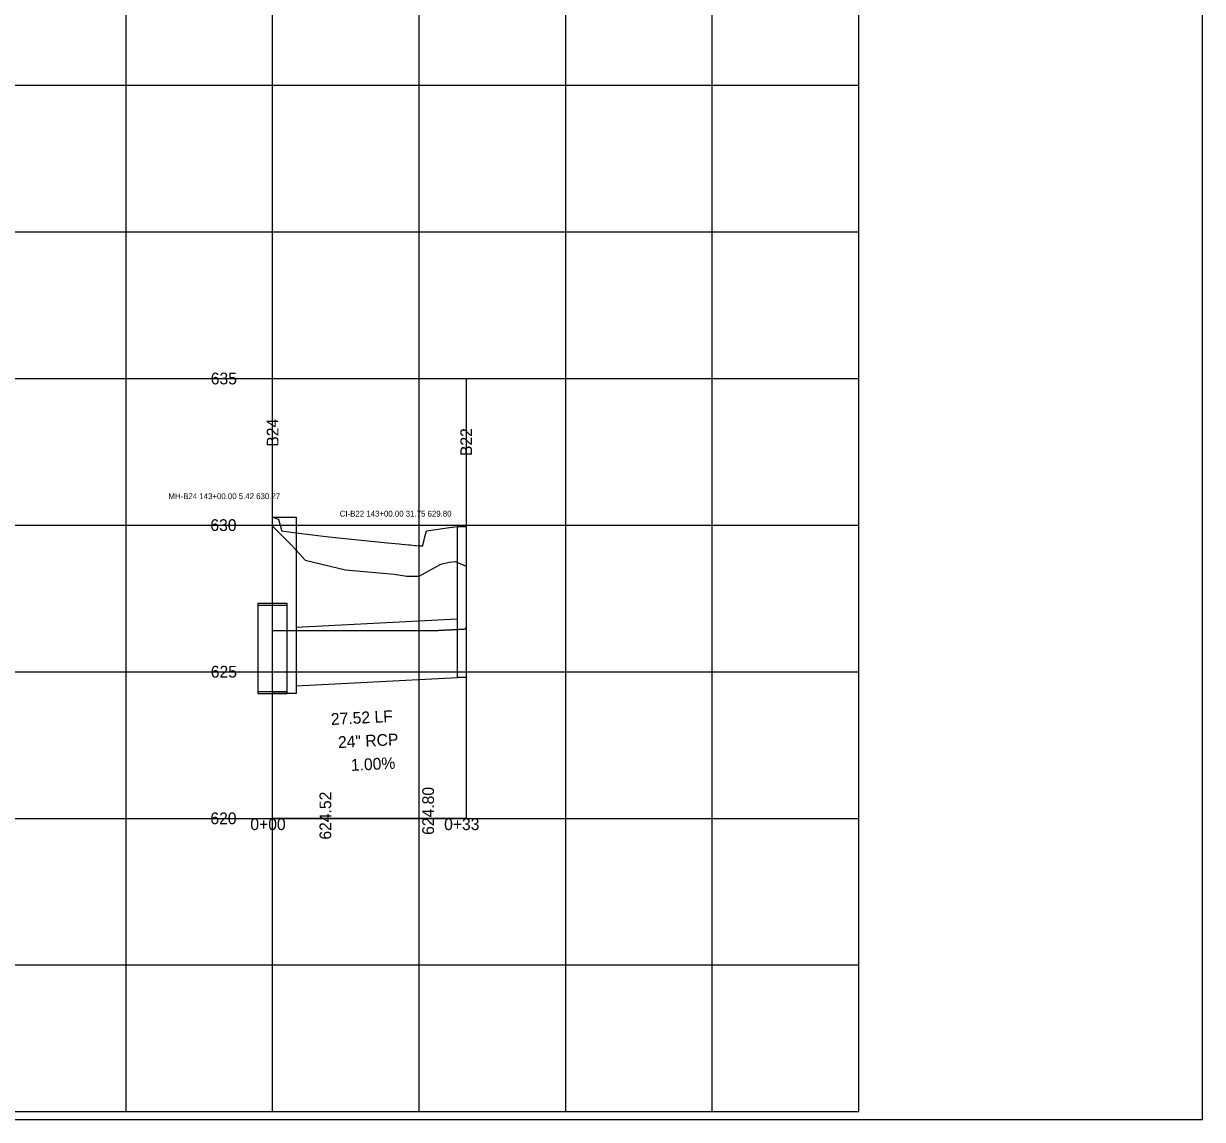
# Model space of a CAD drawing. Extents: x 2253035 to 2279930, y 13774972 to 13793443.
# Drawn here: x 2276931.9 to 2277133, y 13792491.3 to 13792678.1 of the extents above; entities that cross this region are included whole.
import ezdxf

# ---------------------------------------------------------------- set-up
doc = ezdxf.new("R2010")
doc.units = 0
for name, color, linetype in [('Default', 7, 'Continuous'), ('E_Utility_ATT_HH', 7, 'Continuous'), ('E_Utility_ATT_PR_PVC', 7, 'Continuous'), ('E_Utility_Telephone_Manhole Telephone_MHT_point', 7, 'Continuous'), ('E_Utility_Telephone_Telephone Pedestal_TPED_Description', 7, 'Continuous'), ('E_Utility_Water_Water Meter_WM_Description', 7, 'Continuous'), ('E_Utillity_Water_Water Line_12in', 7, 'Continuous'), ('E_Utillity_Water_Water Line_1in', 7, 'Continuous'), ('E_Utillity_Water_Water Line_4in', 7, 'Continuous'), ('E_Utillity_Water_Water Line_8in', 7, 'Continuous')]:
    doc.layers.add(name, color=color, linetype=linetype)

msp = doc.modelspace()

# ---------------------------------------------------------------- linework, layer by layer
at = {"layer": 'Default'}
for p, q in [((2276974.4, 13792592.6), (2277007.43, 13792592.6)), ((2276974.4, 13792567.6), (2277007.43, 13792567.6))]:
    msp.add_line(p, q, dxfattribs=at)
msp.add_lwpolyline([(2276974.4, 13792542.6), (2276974.4, 13792617.6), (2277007.43, 13792617.6), (2277007.43, 13792542.6)], close=True, dxfattribs=at)
at = {"layer": 'E_Utility_ATT_PR_PVC'}
msp.add_lwpolyline([(2276974.4, 13792574.62), (2276974.5, 13792574.62), (2276974.6, 13792574.62), (2276974.7, 13792574.62), (2276974.8, 13792574.62), (2276974.91, 13792574.62), (2276975.01, 13792574.62), (2276975.11, 13792574.62), (2276975.21, 13792574.62), (2276975.31, 13792574.62), (2276975.41, 13792574.62), (2276975.51, 13792574.62), (2276975.61, 13792574.62), (2276975.71, 13792574.62), (2276975.81, 13792574.62), (2276975.91, 13792574.62), (2276976.01, 13792574.62), (2276976.11, 13792574.62), (2276976.21, 13792574.62), (2276976.31, 13792574.62), (2276976.41, 13792574.62), (2276976.51, 13792574.62), (2276976.61, 13792574.62), (2276976.71, 13792574.62), (2276976.81, 13792574.62), (2276976.91, 13792574.62), (2276977.01, 13792574.62), (2276977.11, 13792574.62), (2276977.21, 13792574.62), (2276977.31, 13792574.62), (2276977.41, 13792574.62), (2276977.51, 13792574.62), (2276977.61, 13792574.62), (2276977.71, 13792574.62), (2276977.81, 13792574.62), (2276977.91, 13792574.62), (2276978.01, 13792574.62), (2276978.11, 13792574.62), (2276978.21, 13792574.62), (2276978.31, 13792574.62), (2276978.41, 13792574.62), (2276978.51, 13792574.62), (2276978.61, 13792574.62), (2276978.71, 13792574.62), (2276978.81, 13792574.62), (2276978.91, 13792574.62), (2276979.01, 13792574.62), (2276979.11, 13792574.62), (2276979.21, 13792574.62), (2276979.31, 13792574.62), (2276979.41, 13792574.62), (2276979.51, 13792574.62), (2276979.61, 13792574.62), (2276979.71, 13792574.62), (2276979.81, 13792574.62), (2276979.91, 13792574.62), (2276980.01, 13792574.62), (2276980.11, 13792574.62), (2276980.21, 13792574.62), (2276980.31, 13792574.62), (2276980.41, 13792574.62), (2276980.51, 13792574.62), (2276980.61, 13792574.62), (2276980.71, 13792574.62), (2276980.81, 13792574.62), (2276980.91, 13792574.62), (2276981.01, 13792574.62), (2276981.11, 13792574.62), (2276981.21, 13792574.62), (2276981.31, 13792574.62), (2276981.41, 13792574.62), (2276981.51, 13792574.62), (2276981.61, 13792574.62), (2276981.71, 13792574.62), (2276981.81, 13792574.62), (2276981.91, 13792574.62), (2276982.01, 13792574.62), (2276982.11, 13792574.62), (2276982.21, 13792574.62), (2276982.31, 13792574.62), (2276982.41, 13792574.62), (2276982.51, 13792574.62), (2276982.61, 13792574.62), (2276982.71, 13792574.62), (2276982.81, 13792574.62), (2276982.91, 13792574.62), (2276983.01, 13792574.62), (2276983.11, 13792574.62), (2276983.21, 13792574.62), (2276983.31, 13792574.62), (2276983.41, 13792574.62), (2276983.51, 13792574.62), (2276983.61, 13792574.62), (2276983.71, 13792574.62), (2276983.81, 13792574.62), (2276983.91, 13792574.62), (2276984.01, 13792574.62), (2276984.11, 13792574.62), (2276984.21, 13792574.62), (2276984.31, 13792574.62), (2276984.41, 13792574.62), (2276984.51, 13792574.62), (2276984.61, 13792574.62), (2276984.71, 13792574.62), (2276984.81, 13792574.62), (2276984.91, 13792574.62), (2276985.01, 13792574.62), (2276985.11, 13792574.62), (2276985.21, 13792574.62), (2276985.31, 13792574.62), (2276985.41, 13792574.62), (2276985.51, 13792574.62), (2276985.61, 13792574.62), (2276985.71, 13792574.62), (2276985.81, 13792574.62), (2276985.91, 13792574.62), (2276986.01, 13792574.62), (2276986.11, 13792574.62), (2276986.21, 13792574.62), (2276986.31, 13792574.62), (2276986.41, 13792574.62), (2276986.51, 13792574.62), (2276986.61, 13792574.62), (2276986.71, 13792574.62), (2276986.81, 13792574.62), (2276986.91, 13792574.62), (2276987.01, 13792574.62), (2276987.11, 13792574.62), (2276987.21, 13792574.62), (2276987.31, 13792574.62), (2276987.41, 13792574.62), (2276987.51, 13792574.62), (2276987.61, 13792574.62), (2276987.71, 13792574.62), (2276987.81, 13792574.62), (2276987.91, 13792574.62), (2276988.01, 13792574.62), (2276988.11, 13792574.62), (2276988.21, 13792574.62), (2276988.31, 13792574.62), (2276988.41, 13792574.62), (2276988.51, 13792574.62), (2276988.61, 13792574.62), (2276988.71, 13792574.62), (2276988.81, 13792574.62), (2276988.91, 13792574.62), (2276989.01, 13792574.62), (2276989.11, 13792574.62), (2276989.21, 13792574.62), (2276989.31, 13792574.62), (2276989.41, 13792574.62), (2276989.51, 13792574.62), (2276989.61, 13792574.62), (2276989.71, 13792574.62), (2276989.81, 13792574.62), (2276989.91, 13792574.62), (2276990.01, 13792574.62), (2276990.11, 13792574.62), (2276990.21, 13792574.62), (2276990.31, 13792574.62), (2276990.41, 13792574.62), (2276990.51, 13792574.62), (2276990.61, 13792574.62), (2276990.71, 13792574.62), (2276990.81, 13792574.62), (2276990.91, 13792574.62), (2276991.01, 13792574.62), (2276991.11, 13792574.62), (2276991.21, 13792574.62), (2276991.31, 13792574.62), (2276991.41, 13792574.62), (2276991.51, 13792574.62), (2276991.61, 13792574.62), (2276991.71, 13792574.62), (2276991.81, 13792574.62), (2276991.91, 13792574.62), (2276992.01, 13792574.62), (2276992.11, 13792574.62), (2276992.21, 13792574.62), (2276992.31, 13792574.62), (2276992.41, 13792574.62), (2276992.51, 13792574.62), (2276992.61, 13792574.62), (2276992.71, 13792574.62), (2276992.81, 13792574.62), (2276992.91, 13792574.62), (2276993.01, 13792574.62), (2276993.11, 13792574.62), (2276993.21, 13792574.62), (2276993.31, 13792574.62), (2276993.41, 13792574.62), (2276993.51, 13792574.62), (2276993.61, 13792574.62), (2276993.71, 13792574.62), (2276993.81, 13792574.62), (2276993.91, 13792574.62), (2276994.01, 13792574.62), (2276994.11, 13792574.62), (2276994.21, 13792574.62), (2276994.31, 13792574.62), (2276994.41, 13792574.62), (2276994.51, 13792574.62), (2276994.61, 13792574.62), (2276994.71, 13792574.62), (2276994.81, 13792574.62), (2276994.91, 13792574.62), (2276995.01, 13792574.62), (2276995.11, 13792574.62), (2276995.21, 13792574.62), (2276995.31, 13792574.62), (2276995.41, 13792574.62), (2276995.51, 13792574.62), (2276995.61, 13792574.62), (2276995.71, 13792574.62), (2276995.81, 13792574.62), (2276995.91, 13792574.62), (2276996.01, 13792574.62), (2276996.11, 13792574.62), (2276996.21, 13792574.62), (2276996.31, 13792574.62), (2276996.41, 13792574.62), (2276996.51, 13792574.62), (2276996.61, 13792574.62), (2276996.71, 13792574.62), (2276996.81, 13792574.62), (2276996.91, 13792574.62), (2276997.01, 13792574.62), (2276997.11, 13792574.62), (2276997.21, 13792574.62), (2276997.31, 13792574.62), (2276997.41, 13792574.62), (2276997.51, 13792574.62), (2276997.61, 13792574.62), (2276997.71, 13792574.62), (2276997.81, 13792574.62), (2276997.91, 13792574.62), (2276998.01, 13792574.62), (2276998.11, 13792574.62), (2276998.21, 13792574.62), (2276998.31, 13792574.62), (2276998.41, 13792574.62), (2276998.51, 13792574.62), (2276998.61, 13792574.62), (2276998.71, 13792574.62), (2276998.81, 13792574.62), (2276998.91, 13792574.62), (2276999.01, 13792574.62), (2276999.11, 13792574.62), (2276999.21, 13792574.62), (2276999.31, 13792574.62), (2276999.41, 13792574.62), (2276999.51, 13792574.62), (2276999.61, 13792574.62), (2276999.71, 13792574.62), (2276999.81, 13792574.62), (2276999.91, 13792574.62), (2277000.01, 13792574.62), (2277000.11, 13792574.62), (2277000.21, 13792574.62), (2277000.31, 13792574.62), (2277000.41, 13792574.62), (2277000.51, 13792574.62), (2277000.61, 13792574.62), (2277000.71, 13792574.62), (2277000.81, 13792574.62), (2277000.91, 13792574.62), (2277001.01, 13792574.62), (2277001.11, 13792574.62), (2277001.21, 13792574.62), (2277001.31, 13792574.62), (2277001.41, 13792574.62), (2277001.51, 13792574.62), (2277001.61, 13792574.62), (2277001.71, 13792574.62), (2277001.81, 13792574.62), (2277001.91, 13792574.62), (2277002.01, 13792574.63), (2277002.11, 13792574.63), (2277002.21, 13792574.64), (2277002.31, 13792574.64), (2277002.41, 13792574.65), (2277002.51, 13792574.65), (2277002.61, 13792574.66), (2277002.71, 13792574.66), (2277002.81, 13792574.67), (2277002.91, 13792574.67), (2277003.01, 13792574.68), (2277003.11, 13792574.68), (2277003.21, 13792574.69), (2277003.31, 13792574.69), (2277003.41, 13792574.7), (2277003.51, 13792574.7), (2277003.61, 13792574.71), (2277003.71, 13792574.71), (2277003.81, 13792574.72), (2277003.91, 13792574.72), (2277004.01, 13792574.73), (2277004.11, 13792574.73), (2277004.21, 13792574.74), (2277004.31, 13792574.74), (2277004.41, 13792574.75), (2277004.51, 13792574.75), (2277004.61, 13792574.76), (2277004.71, 13792574.76), (2277004.81, 13792574.77), (2277004.91, 13792574.77), (2277005.01, 13792574.78), (2277005.11, 13792574.78), (2277005.21, 13792574.79), (2277005.31, 13792574.79), (2277005.41, 13792574.8), (2277005.5, 13792574.8), (2277005.6, 13792574.81), (2277005.7, 13792574.81), (2277005.8, 13792574.82), (2277005.9, 13792574.82), (2277006, 13792574.83), (2277006.1, 13792574.83), (2277006.2, 13792574.84), (2277006.3, 13792574.84), (2277006.4, 13792574.85), (2277006.5, 13792574.85), (2277006.6, 13792574.86), (2277006.7, 13792574.86), (2277006.8, 13792574.87), (2277006.9, 13792574.87), (2277007, 13792574.88), (2277007.1, 13792574.88), (2277007.2, 13792574.89), (2277007.3, 13792574.89), (2277007.4, 13792574.9), (2277007.43, 13792574.89), (2277007.43, 13792575.19)], dxfattribs=at)
at = {"layer": 'E_Utility_Telephone_Manhole Telephone_MHT_point'}
for p, q in [((2276949.4, 13792492.6), (2276949.4, 13792792.6)), ((2276974.4, 13792492.6), (2276974.4, 13792792.6)), ((2276999.4, 13792492.6), (2276999.4, 13792792.6)), ((2277024.4, 13792492.6), (2277024.4, 13792792.6)), ((2277049.4, 13792492.6), (2277049.4, 13792792.6)), ((2277074.4, 13792492.6), (2277074.4, 13792792.6)), ((2276749.4, 13792667.6), (2277074.4, 13792667.6)), ((2276749.4, 13792642.6), (2277074.4, 13792642.6)), ((2276749.4, 13792617.6), (2277074.4, 13792617.6)), ((2276749.4, 13792592.6), (2277074.4, 13792592.6)), ((2276749.4, 13792567.6), (2277074.4, 13792567.6)), ((2276749.4, 13792542.6), (2277074.4, 13792542.6)), ((2276749.4, 13792517.6), (2277074.4, 13792517.6)), ((2276749.4, 13792492.6), (2277074.4, 13792492.6))]:
    msp.add_line(p, q, dxfattribs=at)
at = {"layer": 'E_Utility_Water_Water Meter_WM_Description'}
msp.add_lwpolyline([(2277133.03, 13792792.44), (2276749.4, 13792792.44), (2276749.4, 13792491.27), (2277133.03, 13792491.27)], close=True, dxfattribs=at)
at = {"layer": 'E_Utillity_Water_Water Line_12in'}
for points in [[(2276974.4, 13792593.94), (2276978.4, 13792593.94), (2276978.4, 13792563.9), (2276974.4, 13792563.9)], [(2277005.93, 13792592.37), (2277007.43, 13792592.37), (2277007.43, 13792566.6), (2277005.93, 13792566.6)]]:
    msp.add_lwpolyline(points, close=True, dxfattribs=at)
at = {"layer": 'E_Utillity_Water_Water Line_1in'}
msp.add_lwpolyline([(2276974.4, 13792592.4), (2276974.57, 13792592.23), (2276977.45, 13792589.35), (2276978.4, 13792588.32), (2276978.4, 13792588.32), (2276979.95, 13792586.64), (2276986.84, 13792584.96), (2276995.13, 13792584.23), (2276997.27, 13792583.9), (2276999.4, 13792583.91), (2277003.09, 13792585.96), (2277004.5, 13792586.26), (2277005.6, 13792586.38), (2277005.93, 13792586.24), (2277005.93, 13792586.24), (2277007.43, 13792585.58)], dxfattribs=at)
at = {"layer": 'E_Utillity_Water_Water Line_4in'}
for p, q in [((2276978.4, 13792575.22), (2277005.93, 13792576.6)), ((2276978.4, 13792565.22), (2277005.93, 13792566.6))]:
    msp.add_line(p, q, dxfattribs=at)
for points in [[(2276971.9, 13792564.25), (2276976.9, 13792564.25), (2276976.9, 13792579.25), (2276971.9, 13792579.25)], [(2276971.9, 13792563.9), (2276976.9, 13792563.9), (2276976.9, 13792578.9), (2276971.9, 13792578.9)]]:
    msp.add_lwpolyline(points, close=True, dxfattribs=at)
at = {"layer": 'E_Utillity_Water_Water Line_8in'}
msp.add_lwpolyline([(2276974.4, 13792593.94), (2276975.41, 13792593.6), (2276975.42, 13792593.59), (2276975.67, 13792592.6), (2276975.67, 13792592.59), (2276975.93, 13792591.6), (2276978.4, 13792591.29), (2276978.4, 13792591.29), (2276983.97, 13792590.6), (2276984.01, 13792590.6), (2276993.99, 13792589.6), (2276994, 13792589.6), (2276994, 13792589.6), (2276995.98, 13792589.4), (2276996.37, 13792589.36), (2276997.65, 13792589.23), (2276997.84, 13792589.22), (2276998.74, 13792589.12), (2276998.83, 13792589.12), (2276999.52, 13792589.05), (2276999.54, 13792589.04), (2276999.63, 13792589.04), (2276999.99, 13792589.04), (2276999.99, 13792589.05), (2277000, 13792589.06), (2277000, 13792589.08), (2277000.01, 13792589.11), (2277000.01, 13792589.12), (2277000.02, 13792589.14), (2277000.03, 13792589.18), (2277000.03, 13792589.19), (2277000.03, 13792589.22), (2277000.05, 13792589.27), (2277000.06, 13792589.32), (2277000.07, 13792589.36), (2277000.11, 13792589.49), (2277000.13, 13792589.6), (2277000.13, 13792589.6), (2277000.39, 13792590.6), (2277000.65, 13792591.6), (2277000.65, 13792591.6), (2277000.65, 13792591.6), (2277004.55, 13792592.17), (2277005.93, 13792592.37), (2277005.93, 13792592.37), (2277007.43, 13792592.58)], dxfattribs=at)

# ---------------------------------------------------------------- texts
at = {"layer": 'Default'}
for s, p in [('635', (2276963.85, 13792616.6)), ('630', (2276963.78, 13792591.6)), ('625', (2276963.85, 13792566.6)), ('620', (2276963.78, 13792541.6)), ('0+00', (2276970.6, 13792540.6)), ('0+33', (2277003.66, 13792540.6))]:
    msp.add_text(s, height=2, dxfattribs=at).set_placement(p)
at = {"layer": 'E_Utility_ATT_HH'}
for s, rotation, p in [('B24', 90, (2276975.4, 13792605.97)), ('B22', 90, (2277008.43, 13792604.38)), ('27.52 LF', 2.8624, (2276984.39, 13792558.52)), ('24" RCP', 2.8624, (2276985.6, 13792554.58)), ('1.00%', 2.8624, (2276987.8, 13792550.68)), ('624.80', 90, (2277001.93, 13792539.78)), ('624.52', 90, (2276984.4, 13792538.97))]:
    msp.add_text(s, height=2, rotation=rotation, dxfattribs=at).set_placement(p)
at = {"layer": 'E_Utility_Telephone_Telephone Pedestal_TPED_Description'}
for s, p in [('MH-B24 143+00.00 5.42 630.27', (2276956.62, 13792597.03)), ('CI-B22 143+00.00 31.75 629.80', (2276985.85, 13792594.05))]:
    msp.add_text(s, height=1, rotation=0, dxfattribs=at).set_placement(p)

doc.saveas('drawing.dxf')
